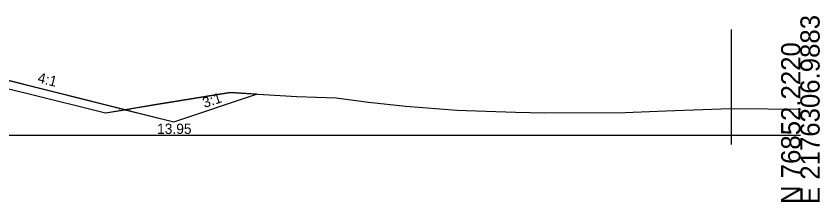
# Model space of a CAD drawing. Extents: x 2177029 to 2201446, y 59897 to 78390.
# Drawn here: x 2199328.6 to 2199445.6, y 67897.6 to 67924.6 of the extents above; entities that cross this region are included whole.
import ezdxf

# ---------------------------------------------------------------- set-up
doc = ezdxf.new("R2010")
doc.units = 0
for name, color, linetype in [('Exist Cross Section Cell', 7, 'Continuous'), ('Exist PHM Roadway Shape', 7, 'Continuous'), ('Exist XS Ground Line', 7, 'Continuous'), ('Prop CMT Guardrail Widen Shoulder', 7, 'Continuous'), ('Prop CMT Top Wall Envelope', 7, 'Continuous'), ('Prop Hatching', 7, 'Continuous'), ('Prop XS Side Slope Text', 7, 'Continuous'), ('Scratch_Level_2', 7, 'Continuous')]:
    doc.layers.add(name, color=color, linetype=linetype)

msp = doc.modelspace()

# ---------------------------------------------------------------- linework, layer by layer
at = {"layer": 'Exist Cross Section Cell'}
msp.add_line((2199242.73, 67907.31), (2199442.73, 67907.31), dxfattribs=at)
at = {"layer": 'Exist XS Ground Line'}
msp.add_lwpolyline([(2199320.5, 67915.73), (2199330.34, 67913.37), (2199341.61, 67910.55), (2199348.73, 67911.71), (2199359.77, 67913.5), (2199369.46, 67912.93), (2199375.19, 67912.77), (2199379.89, 67912.11), (2199385.31, 67911.54), (2199392.72, 67910.97), (2199401.27, 67910.68), (2199405.55, 67910.56), (2199417.22, 67910.63), (2199418.38, 67910.65), (2199423.17, 67910.84), (2199431.22, 67911.15), (2199433.17, 67911.19), (2199442.73, 67911.12)], dxfattribs=at)
at = {"layer": 'Prop Hatching'}
msp.add_line((2199351.55, 67909.26), (2199363.6, 67913.28), dxfattribs=at)
msp.add_lwpolyline([(2199318.74, 67916.96), (2199320.74, 67916.96), (2199351.55, 67909.26)], dxfattribs=at)
at = {"layer": 'Prop XS Side Slope Text'}
for points in [[(2199341.61, 67910.55), (2199344.5, 67911.02), (2199324.74, 67915.96), (2199319.74, 67915.96), (2199316.15, 67915.96), (2199317.83, 67915.87), (2199320.5, 67915.73), (2199330.34, 67913.37)], [(2199351.55, 67909.26), (2199363.6, 67913.28), (2199359.77, 67913.5), (2199348.73, 67911.71), (2199344.5, 67911.02)]]:
    msp.add_lwpolyline(points, close=True, dxfattribs=at)
at = {"layer": 'Scratch_Level_2'}
msp.add_line((2199432.73, 67905.94), (2199432.73, 67922.68), dxfattribs=at)

# ---------------------------------------------------------------- texts
at = {"layer": 'Exist Cross Section Cell'}
for s, p in [('E 2176306.9883', (2199445.53, 67897.31)), ('N 76852.2220', (2199442.73, 67897.31))]:
    msp.add_text(s, height=2.8, rotation=90, dxfattribs=at).set_placement(p)
at = {"layer": 'Exist PHM Roadway Shape'}
msp.add_text('RT_Slope_Fill', height=0.2, dxfattribs=at).set_placement((2199343.55, 67910.92))
at = {"layer": 'Prop CMT Guardrail Widen Shoulder'}
msp.add_text('4:1', height=1.5, rotation=345.962, dxfattribs=at).set_placement((2199331.65, 67915.01))
at = {"layer": 'Prop CMT Top Wall Envelope'}
msp.add_text('3:1', height=1.5, rotation=18.4349, dxfattribs=at).set_placement((2199356.03, 67911.26))
msp.add_text('13.95', height=1.5, dxfattribs=at).set_placement((2199349.13, 67907.5))

doc.saveas('drawing.dxf')
